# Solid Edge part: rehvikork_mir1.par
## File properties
Author: KULL
Template: Iso Metric Part.par
Last saved by: KULL
Revision: 2
Application: Solid Edge
Accuracy: 0,990
Username: KULL
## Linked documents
rehvikork.par
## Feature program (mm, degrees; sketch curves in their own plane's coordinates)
part copy "CopiedPart_1"
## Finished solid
Body 1: solid body, 93 faces, 217 edges, 128 vertices.
  Faces by surface: blend 40, spline 40, sphere 6, torus 3, cylinder 2, cone 1, plane 1
  Edges by curve: intersection 128, circle 49, line 40
Bounding box of the edges (mm; curved faces can reach further): 4.951 x 16.000 x 16.000, from (-4, -8, -8) to (0.951, 8, 8).
Cylindrical faces by radius (mm): R7 x1, R8 x1
Conical faces (half-angle, radius in mm at the cone's reference point): 11.8765 deg R7 x1
Toroidal faces (ring radius, tube radius in mm): R7.0618 r0.08 x1, R7.6 r0.4 x1, R7.92 r0.08 x1
Spherical faces by radius (mm): R33.0132 x1, R33.5132 x2, R34.0132 x3
Planar faces by outward normal: -x 1
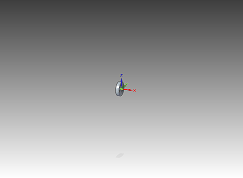
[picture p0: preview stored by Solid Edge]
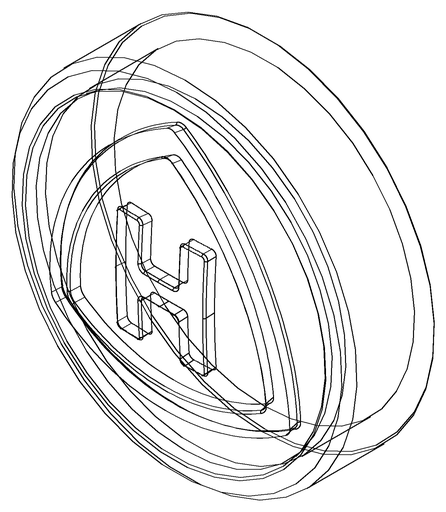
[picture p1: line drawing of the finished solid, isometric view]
